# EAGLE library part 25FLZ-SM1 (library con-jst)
CONNECTOR
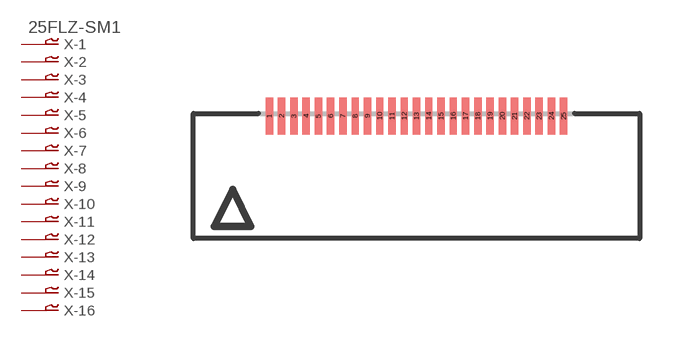
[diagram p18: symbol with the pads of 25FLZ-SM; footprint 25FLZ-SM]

Designator prefix X; gates -1=P-VN -2=P-N -3=P-N -4=P-N -5=P-N -6=P-N -7=P-N -8=P-N -9=P-N -10=P-N -11=P-N -12=P-N -13=P-N -14=P-N -15=P-N -16=P-N -17=P-N -18=P-N -19=P-N -20=P-N -21=P-N -22=P-N -23=P-N -24=P-N -25=P-N

## 25FLZ-SM1 (OC_FARNELL: unknown; OC_NEWARK: unknown)  [25FLZ-SM]
1  -1:1  pas
2  -2:1  pas
3  -3:1  pas
4  -4:1  pas
5  -5:1  pas
6  -6:1  pas
7  -7:1  pas
8  -8:1  pas
9  -9:1  pas
10  -10:1  pas
11  -11:1  pas
12  -12:1  pas
13  -13:1  pas
14  -14:1  pas
15  -15:1  pas
16  -16:1  pas
17  -17:1  pas
18  -18:1  pas
19  -19:1  pas
20  -20:1  pas
21  -21:1  pas
22  -22:1  pas
23  -23:1  pas
24  -24:1  pas
25  -25:1  pas

## Footprint 25FLZ-SM (pad centres in mm)
CONNECTOR
smd 0.3 x 1.5: 1 -6,2.5; 2 -5.5,2.5; 3 -5,2.5; 4 -4.5,2.5; 5 -4,2.5; 6 -3.5,2.5; 7 -3,2.5; 8 -2.5,2.5; 9 -2,2.5; 10 -1.5,2.5; 11 -1,2.5; 12 -0.5,2.5; 13 0,2.5; 14 0.5,2.5; 15 1,2.5; 16 1.5,2.5; 17 2,2.5; 18 2.5,2.5; 19 3,2.5; 20 3.5,2.5; 21 4,2.5; 22 4.5,2.5; 23 5,2.5; 24 5.5,2.5; 25 6,2.5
